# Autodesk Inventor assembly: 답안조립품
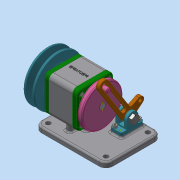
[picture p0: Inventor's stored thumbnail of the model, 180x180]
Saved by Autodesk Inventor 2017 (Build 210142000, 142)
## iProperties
Part Number: 답안조립품
Material: 일반
Document SubType Name: Assembly
Designer: 7-1
Author: 7-1
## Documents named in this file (19)
- C:\Users\7-1\Desktop\601106V1029\답안조립품.iam
- C:\Users\7-1\Desktop\601106V1029\본체.ipt
- C:\Users\7-1\Desktop\601106V1029\V-벨트풀리.ipt
- C:\Users\7-1\Desktop\601106V1029\너트 M8.ipt
- C:\Users\7-1\Desktop\601106V1029\너트 M10x1.ipt
- C:\Users\7-1\Desktop\601106V1029\돌림판.ipt
- C:\Users\7-1\Desktop\601106V1029\멈춤나사 M3x5.ipt
- C:\Users\7-1\Desktop\601106V1029\베어링 6004.ipt
- C:\Users\7-1\Desktop\601106V1029\볼트 M4.ipt
- C:\Users\7-1\Desktop\601106V1029\오일 실 17 30 5.ipt
- C:\Users\7-1\Desktop\601106V1029\와셔 8x15.5.ipt
- C:\Users\7-1\Desktop\601106V1029\축.ipt
- C:\Users\7-1\Desktop\601106V1029\커버.ipt
- C:\Users\7-1\Desktop\601106V1029\크랭크.ipt
- C:\Users\7-1\Desktop\601106V1029\키 4 x 4 x 8.ipt
- C:\Users\7-1\Desktop\601106V1029\키 5 x 5 x 12.ipt
- C:\Users\7-1\Desktop\601106V1029\핀 3 x 8.ipt
- C:\Users\7-1\Desktop\601106V1029\힌지 축.ipt
- C:\Users\7-1\Desktop\601106V1029\힌지.ipt
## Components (3 placed, 2 different names)
1. V-벨트풀리:1
2. 핀 3 x 8:1 — 플러쉬:3
3. 핀 3 x 8:2 — 플러쉬:4
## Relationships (2: Flush 2)
- 플러쉬:3 [Flush]: 핀 3 x 8:1
- 플러쉬:4 [Flush]: 핀 3 x 8:2
